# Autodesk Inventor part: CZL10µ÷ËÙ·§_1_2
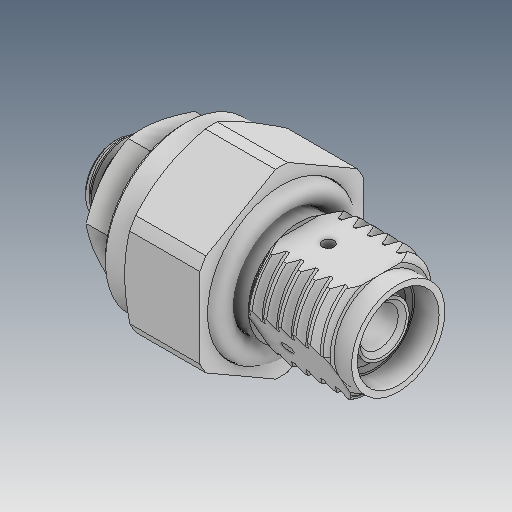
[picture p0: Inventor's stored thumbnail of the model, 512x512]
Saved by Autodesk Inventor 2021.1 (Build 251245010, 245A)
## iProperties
Created: 2019-04
Part Number: CZL10µ÷ËÙ·§_1_2
Material: Ogólny
Document SubType Name: Modeling
Designer: user
Density: 1 g/cm^3
Appearance: Domyślna
Author: user
Revision Number: ÈÎºÎ
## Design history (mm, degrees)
feature "ÊäÈë1"
feature "ÊäÈë2"
feature "ÊäÈë3"
node "Bryła1"
node "Bryła2"
node "Bryła3"
